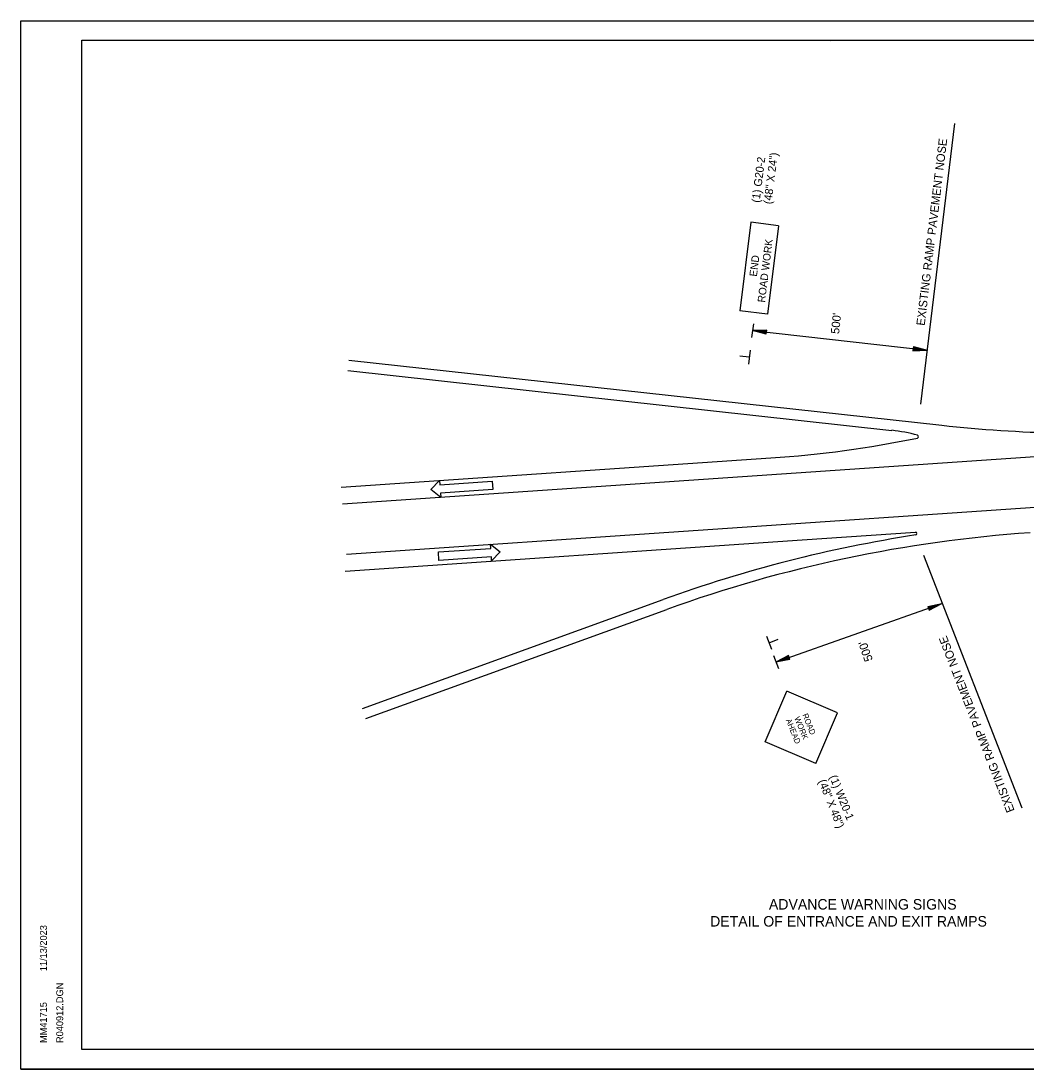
# Model space of a CAD drawing. Extents: x 13744624 to 13747958, y 3814079 to 3815145.
# Drawn here: x 13746291 to 13747314, y 3814079 to 3815145 of the extents above; entities that cross this region are included whole.
import ezdxf

# ---------------------------------------------------------------- set-up
doc = ezdxf.new("R2010")
doc.units = 0
for name, color, linetype in [('Default', 7, 'Continuous'), ('R_Border', 7, 'Continuous'), ('R_Draft', 7, 'Continuous'), ('R_Exist Surface', 7, 'Continuous'), ('R_MOT', 7, 'Continuous'), ('R_No Plot', 7, 'Continuous')]:
    doc.layers.add(name, color=color, linetype=linetype)

msp = doc.modelspace()

# ---------------------------------------------------------------- linework, layer by layer
at = {"layer": 'R_Border'}
for p, q in [((13746352.9, 3815125.9), (13747933.8, 3815125.9)), ((13746352.9, 3814098.6), (13746352.9, 3815125.9)), ((13747115.5, 3815124.6), (13747115.5, 3815124.6)), ((13747115.5, 3815124.6), (13747115.5, 3815124.6)), ((13746352.9, 3814098.6), (13746352.9, 3814098.6)), ((13747933.8, 3814098.6), (13746352.9, 3814098.6))]:
    msp.add_line(p, q, dxfattribs=at)
at = {"layer": 'R_Draft'}
for p, q in [((13747050.1, 3814830.8), (13747035.7, 3814830.2)), ((13747050.1, 3814830.8), (13747035.7, 3814830.2)), ((13747049.7, 3814826.5), (13747035.7, 3814830.2)), ((13747049.7, 3814826.5), (13747035.7, 3814830.2)), ((13747050.1, 3814830.4), (13747038.1, 3814830)), ((13747050.1, 3814830.4), (13747038.1, 3814830)), ((13747049.7, 3814826.9), (13747038.1, 3814830)), ((13747049.7, 3814826.9), (13747038.1, 3814830)), ((13747050.1, 3814830.1), (13747040.5, 3814829.7)), ((13747050.1, 3814830.1), (13747040.5, 3814829.7)), ((13747049.8, 3814827.2), (13747040.5, 3814829.7)), ((13747049.8, 3814827.2), (13747040.5, 3814829.7)), ((13747050, 3814829.7), (13747042.9, 3814829.4)), ((13747050, 3814829.7), (13747042.9, 3814829.4)), ((13747049.8, 3814827.6), (13747042.9, 3814829.4)), ((13747049.8, 3814827.6), (13747042.9, 3814829.4)), ((13747050, 3814829.3), (13747045.3, 3814829.2)), ((13747050, 3814829.3), (13747045.3, 3814829.2)), ((13747049.8, 3814828), (13747045.3, 3814829.2)), ((13747049.8, 3814828), (13747045.3, 3814829.2)), ((13747049.9, 3814829), (13747047.7, 3814828.9)), ((13747049.9, 3814829), (13747047.7, 3814828.9)), ((13747049.9, 3814828.3), (13747047.7, 3814828.9)), ((13747049.9, 3814828.3), (13747047.7, 3814828.9)), ((13747049.7, 3814826.5), (13747050.1, 3814830.8)), ((13747049.7, 3814826.5), (13747050.1, 3814830.8)), ((13747199.5, 3814814), (13747199, 3814809.7)), ((13747199, 3814810.1), (13747211.1, 3814810.5)), ((13747199, 3814809.7), (13747213.4, 3814810.2)), ((13747199.1, 3814810.8), (13747206.3, 3814811)), ((13747199.1, 3814810.4), (13747208.6, 3814810.8)), ((13747199.2, 3814811.5), (13747201.5, 3814811.6)), ((13747199.2, 3814811.1), (13747203.8, 3814811.3)), ((13747199.3, 3814812.5), (13747203.8, 3814811.3)), ((13747199.3, 3814812.2), (13747201.5, 3814811.6)), ((13747199.4, 3814813.6), (13747211.1, 3814810.5)), ((13747199.4, 3814813.2), (13747208.6, 3814810.8)), ((13747199.4, 3814812.9), (13747206.3, 3814811)), ((13747199.5, 3814814), (13747213.4, 3814810.2)), ((13747214.1, 3814549.6), (13747228.3, 3814552.4)), ((13747214.2, 3814549.3), (13747226, 3814551.6)), ((13747215.4, 3814545.9), (13747226, 3814551.6)), ((13747215.5, 3814545.6), (13747228.3, 3814552.4)), ((13747214.1, 3814549.6), (13747215.5, 3814545.6)), ((13747214.3, 3814549), (13747223.7, 3814550.8)), ((13747214.5, 3814548.6), (13747221.5, 3814550)), ((13747214.6, 3814548.3), (13747219.2, 3814549.2)), ((13747214.7, 3814547.9), (13747216.9, 3814548.4)), ((13747214.9, 3814547.3), (13747216.9, 3814548.4)), ((13747215.1, 3814547), (13747219.2, 3814549.2)), ((13747215.2, 3814546.6), (13747221.5, 3814550)), ((13747215.3, 3814546.3), (13747223.7, 3814550.8)), ((13747072.3, 3814499.7), (13747059.5, 3814492.9)), ((13747072.4, 3814499.3), (13747061.8, 3814493.7)), ((13747072.5, 3814499), (13747064.1, 3814494.5)), ((13747072.6, 3814498.6), (13747066.3, 3814495.3)), ((13747072.7, 3814498.3), (13747068.6, 3814496.1)), ((13747072.9, 3814498), (13747070.8, 3814496.9)), ((13747073.7, 3814495.6), (13747072.3, 3814499.7)), ((13747073.7, 3814495.6), (13747059.5, 3814492.9)), ((13747060.8, 3814493.6), (13747059.5, 3814492.9)), ((13747060.9, 3814493.2), (13747059.5, 3814492.9)), ((13747060.8, 3814493.5), (13747059.7, 3814493)), ((13747060.9, 3814493.2), (13747059.7, 3814493)), ((13747060.8, 3814493.5), (13747060, 3814493)), ((13747060.9, 3814493.2), (13747060, 3814493)), ((13747060.8, 3814493.5), (13747060.2, 3814493.1)), ((13747060.9, 3814493.3), (13747060.2, 3814493.1)), ((13747060.8, 3814493.4), (13747060.4, 3814493.2)), ((13747060.9, 3814493.3), (13747060.4, 3814493.2)), ((13747060.8, 3814493.4), (13747060.6, 3814493.3)), ((13747060.9, 3814493.3), (13747060.6, 3814493.3)), ((13747060.9, 3814493.2), (13747060.8, 3814493.6)), ((13747073.6, 3814496), (13747061.8, 3814493.7)), ((13747073.5, 3814496.3), (13747064.1, 3814494.5)), ((13747073.3, 3814496.6), (13747066.3, 3814495.3)), ((13747073.2, 3814497), (13747068.6, 3814496.1)), ((13747073.1, 3814497.3), (13747070.8, 3814496.9))]:
    msp.add_line(p, q, dxfattribs=at)
at = {"layer": 'R_Exist Surface'}
for p, q in [((13746624.8, 3814800.2), (13747228.3, 3814733.9)), ((13746623.8, 3814789.5), (13747177.4, 3814728.7)), ((13746618.3, 3814653.8), (13747556.5, 3814717.9)), ((13746616.9, 3814670.9), (13747054.4, 3814700.7)), ((13746622.2, 3814602.8), (13747576.4, 3814667.9)), ((13746620.9, 3814585.5), (13747086.3, 3814617.3)), ((13747086.3, 3814617.3), (13747201.5, 3814625.1)), ((13746638.5, 3814445.7), (13746944.6, 3814556.5)), ((13746642.1, 3814435.6), (13746948.3, 3814546.5))]:
    msp.add_line(p, q, dxfattribs=at)
for centre, radius, start, end in [((13747376.6, 3816084.6), 1358.8, 263.7335, 273.9), ((13747161.3, 3814574.3), 155.3, 74.1458, 84.0343), ((13747203.3, 3814722.3), 1.43, 281.6258, 73.5312), ((13746978.9, 3815819.3), 1121.2, 273.8643, 281.5623), ((13747410.9, 3813268.8), 1369.5, 98.7808, 109.9033), ((13747410.9, 3813268.8), 1358.8, 93.9033, 109.9033), ((13747201.6, 3814623.7), 1.43, 278.7808, 93.9002)]:
    msp.add_arc(centre, radius, start, end, dxfattribs=at)
at = {"layer": 'R_MOT'}
for p, q in [((13747241.4, 3815041), (13747206.8, 3814755.3)), ((13747033.8, 3814940.5), (13747022.8, 3814850.5)), ((13747062.1, 3814937), (13747033.8, 3814940.5)), ((13747062.1, 3814937), (13747051, 3814847.1)), ((13747051, 3814847.1), (13747022.8, 3814850.5)), ((13747036.6, 3814837.3), (13747034.8, 3814823.1)), ((13747035.7, 3814830.2), (13747213.4, 3814810.2)), ((13747033.2, 3814810.3), (13747031.6, 3814796.2)), ((13747032.4, 3814803.3), (13747022.6, 3814804.4)), ((13746708.2, 3814668.4), (13746717, 3814677.6)), ((13746718.2, 3814660.5), (13746708.2, 3814668.4)), ((13746717, 3814677.6), (13746717.3, 3814673.3)), ((13746717.3, 3814673.3), (13746770.7, 3814676.9)), ((13746771.3, 3814668.4), (13746717.9, 3814664.7)), ((13746770.7, 3814676.9), (13746771.3, 3814668.4)), ((13746717.9, 3814664.7), (13746718.2, 3814660.5)), ((13746715.9, 3814605), (13746769.3, 3814608.6)), ((13746716.4, 3814596.4), (13746715.9, 3814605)), ((13746769.3, 3814608.6), (13746769, 3814612.9)), ((13746769, 3814612.9), (13746778.9, 3814605)), ((13746778.9, 3814605), (13746770.1, 3814595.8)), ((13746769.8, 3814600), (13746716.4, 3814596.4)), ((13746770.1, 3814595.8), (13746769.8, 3814600)), ((13747209.7, 3814601.8), (13747309.9, 3814344.7)), ((13747059.5, 3814492.9), (13747228.3, 3814552.4)), ((13747050, 3814519.1), (13747055, 3814505.9)), ((13747052.5, 3814512.5), (13747061.7, 3814516.1)), ((13747057, 3814499.6), (13747062, 3814486.2)), ((13747048.4, 3814411.6), (13747070.5, 3814463.3)), ((13747122.2, 3814441.3), (13747070.5, 3814463.3)), ((13747100.2, 3814389.5), (13747122.2, 3814441.3)), ((13747100.2, 3814389.5), (13747048.4, 3814411.6))]:
    msp.add_line(p, q, dxfattribs=at)
at = {"layer": 'R_No Plot'}
for p, q in [((13746290.9, 3815145.4), (13747957.6, 3815145.4)), ((13746290.9, 3814078.7), (13747957.6, 3814078.7))]:
    msp.add_line(p, q, dxfattribs=at)
for points in [[(13746290.9, 3815145.4), (13747957.6, 3815145.4), (13747957.6, 3814078.7), (13746290.9, 3814078.7)], [(13747522.5, 3815125.9), (13747620.6, 3815125.9), (13747620.6, 3815076.5), (13747701.2, 3815076.5), (13747817.2, 3815076.5), (13747817.2, 3814954.9), (13747933.8, 3814954.9), (13747933.8, 3814098.6), (13746352.9, 3814098.6), (13746352.9, 3815125.9)]]:
    msp.add_lwpolyline(points, close=True, dxfattribs=at)

# ---------------------------------------------------------------- texts
at = {"layer": 'Default'}
for s, p in [('ADVANCE WARNING SIGNS', (13747052.4, 3814241)), ('DETAIL OF ENTRANCE AND EXIT RAMPS', (13746992.5, 3814223.7))]:
    msp.add_text(s, height=10.714, dxfattribs=at).set_placement(p)
at = {"layer": 'R_Border'}
for s, p in [('11/13/2023', (13746317.3, 3814178.3)), ('R040912.DGN', (13746333.9, 3814105.2)), ('MM41715', (13746317.3, 3814105.2))]:
    msp.add_text(s, height=7, rotation=90, dxfattribs=at).set_placement(p)
at = {"layer": 'R_MOT'}
for s, height, rotation, p in [('EXISTING RAMP PAVEMENT NOSE', 8.571, 83.096, (13747210.9, 3814834.9)), ('(48" X 24")', 8.184, 82.6881, (13747054.9, 3814958.6)), ('(1) G20-2', 8.18, 82.6881, (13747042.8, 3814960.1)), ('ROAD WORK', 7.73, 82.996, (13747048.4, 3814858.5)), ('END', 7.73, 82.996, (13747040.1, 3814884.9)), ("500'", 8.57, 83.8888, (13747123.8, 3814826.5)), ('EXISTING RAMP PAVEMENT NOSE', 8.571, 111.285, (13747302.7, 3814341.8)), ("500'", 8.57, 109.4135, (13747158.3, 3814495.2)), ('AHEAD', 5.86, 291.9292, (13747069.4, 3814434)), ('WORK', 5.86, 291.9287, (13747078.1, 3814436)), ('ROAD', 5.86, 291.9291, (13747086.3, 3814439.2)), ('(48" X 48")', 8.143, 291.9287, (13747102.5, 3814371.6)), ('(1) W20-1', 8.14, 291.9287, (13747113.8, 3814376.1))]:
    msp.add_text(s, height=height, rotation=rotation, dxfattribs=at).set_placement(p)

doc.saveas('drawing.dxf')
